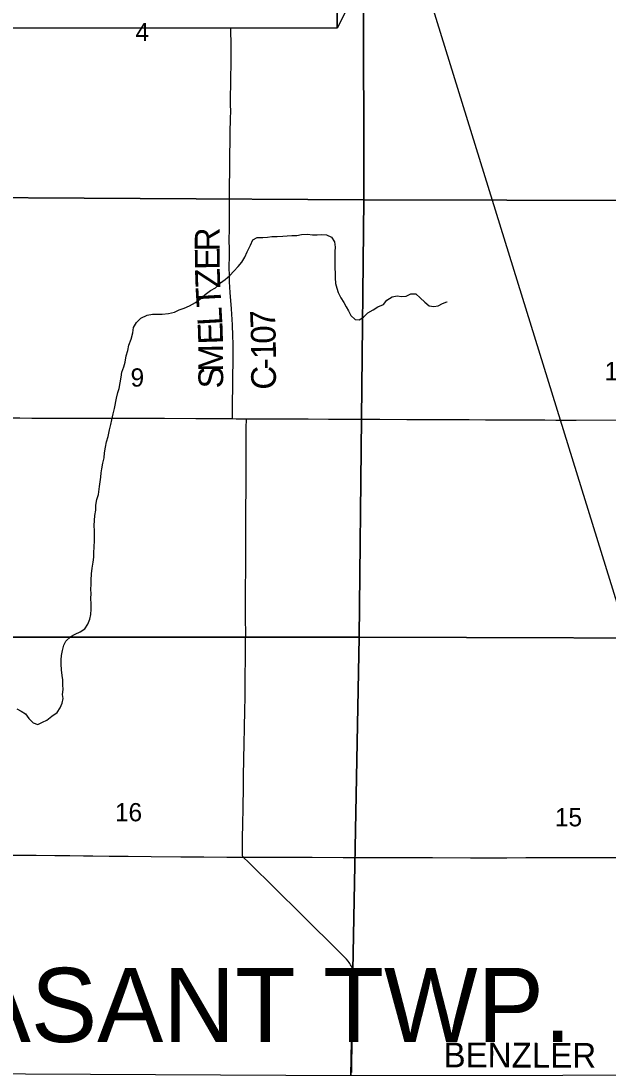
# Model space of a CAD drawing. Extents: x -97 to 34, y -21 to 22.
# Drawn here: x 4.799 to 6.147, y 14.464 to 16.869 of the extents above; entities that cross this region are included whole.
import ezdxf

# ---------------------------------------------------------------- set-up
doc = ezdxf.new("R2010")
doc.units = 0
for name, color, linetype in [('GM_X_County_Road', 7, 'Continuous'), ('GM_X_County_Road_Text', 7, 'Continuous'), ('GM_X_Minor_River', 7, 'Continuous'), ('GM_X_Rail_Line', 7, 'Continuous'), ('GM_X_Section', 7, 'Continuous'), ('GM_X_Section_Text', 7, 'Continuous'), ('GM_X_Township_Road_Text', 7, 'Continuous'), ('GM_X_Township_Text', 7, 'Continuous'), ('SH_Text', 7, 'Continuous')]:
    doc.layers.add(name, color=color, linetype=linetype)

msp = doc.modelspace()

# ---------------------------------------------------------------- linework, layer by layer
at = {"layer": 'GM_X_County_Road'}
for points in [[(5.285, 15.9558), (5.285, 15.9593), (5.2849, 15.9815), (5.2859, 16.0405), (5.2866, 16.0996), (5.2864, 16.1276), (5.286, 16.1462), (5.285, 16.1711), (5.2827, 16.2082), (5.28, 16.2455), (5.2784, 16.2703), (5.2778, 16.2858), (5.2776, 16.3013), (5.2778, 16.3324), (5.2778, 16.3446), (5.2777, 16.3664), (5.2779, 16.3913), (5.2779, 16.41), (5.278, 16.4255), (5.2783, 16.4659), (5.2785, 16.4846), (5.2784, 16.497), (5.2786, 16.5187), (5.2789, 16.5436), (5.279, 16.556), (5.2796, 16.5995), (5.28, 16.6119), (5.2808, 16.6461), (5.2809, 16.6616), (5.2808, 16.6772), (5.2807, 16.6896), (5.2808, 16.6989), (5.281, 16.7206), (5.2812, 16.7362), (5.2813, 16.7393), (5.2813, 16.7424), (5.2816, 16.7672), (5.2817, 16.7765), (5.2816, 16.7827), (5.2817, 16.7858), (5.2817, 16.7889), (5.2817, 16.792), (5.2819, 16.8106), (5.2812, 16.8527)], [(4.594, 15.9594), (4.6195, 15.9589), (4.6537, 15.9584), (4.6851, 15.958), (4.7283, 15.9579), (4.7625, 15.9577), (4.7967, 15.9573), (4.8246, 15.957), (4.8495, 15.9569), (4.8619, 15.9569), (4.9054, 15.9566), (4.9458, 15.9566), (4.9862, 15.9567), (5.0235, 15.9568), (5.0577, 15.9568), (5.0918, 15.9568), (5.1291, 15.9569), (5.2006, 15.9563), (5.2565, 15.9559), (5.285, 15.9558)], [(5.285, 15.9558), (5.2938, 15.9557), (5.3173, 15.9556)], [(5.3139, 15.3297), (5.3139, 15.3328), (5.3141, 15.3639), (5.3146, 15.4043), (5.3151, 15.4478), (5.3153, 15.4634), (5.315, 15.4945), (5.3149, 15.5287), (5.3152, 15.5691), (5.3155, 15.6064), (5.3154, 15.6189), (5.3154, 15.6344), (5.3154, 15.6624), (5.3158, 15.7059), (5.3159, 15.7339), (5.316, 15.7557), (5.3161, 15.7865), (5.3162, 15.8024), (5.3164, 15.8241), (5.3165, 15.8677), (5.3164, 15.8956), (5.3164, 15.9174), (5.3165, 15.9268), (5.3167, 15.9359), (5.3172, 15.9529), (5.3173, 15.9556)], [(5.3173, 15.9556), (5.328, 15.9555), (5.4181, 15.9551), (5.4585, 15.9551), (5.5051, 15.9549), (5.6232, 15.9543), (5.6854, 15.9539), (5.7476, 15.954), (5.7817, 15.9537), (5.8284, 15.9536), (5.8656, 15.9532), (5.8998, 15.9533), (5.9713, 15.9531), (6.0024, 15.9528), (6.0272, 15.9524), (6.0397, 15.9524), (6.0738, 15.9525), (6.1795, 15.9528)], [(5.31, 14.948), (5.3095, 14.9486), (5.3088, 14.9498), (5.3082, 14.9512), (5.3078, 14.9525), (5.3076, 14.954), (5.3076, 14.9554), (5.3079, 14.9833), (5.309, 15.033), (5.3094, 15.0516), (5.3094, 15.0703), (5.3099, 15.1013), (5.3105, 15.1355), (5.312, 15.21), (5.3124, 15.2442), (5.3133, 15.2876), (5.3138, 15.3138), (5.3139, 15.3297)], [(4.5259, 14.9544), (4.5326, 14.9543), (4.5823, 14.9538), (4.6444, 14.9529), (4.7034, 14.9529), (4.7314, 14.9528), (4.7749, 14.9529), (4.8339, 14.9526), (4.8773, 14.952), (4.9115, 14.9519), (4.9426, 14.9516), (4.9643, 14.9513), (5.0016, 14.9509), (5.0451, 14.9504), (5.0979, 14.9499), (5.1663, 14.9494), (5.2191, 14.949), (5.2719, 14.9485), (5.31, 14.948)], [(5.31, 14.948), (5.3154, 14.948), (5.3558, 14.9483), (5.4677, 14.9483), (5.5392, 14.9479), (5.6168, 14.9479), (5.6665, 14.9473), (5.6883, 14.9473), (5.7442, 14.9474), (5.8313, 14.9469), (5.8748, 14.9466), (5.8965, 14.9467), (5.9152, 14.9468), (5.9587, 14.9473), (5.9866, 14.9473), (6.0612, 14.9474), (6.1762, 14.9477), (6.2166, 14.9476), (6.2694, 14.9473), (6.2946, 14.9471)], [(5.5587, 14.4535), (5.5592, 14.4815), (5.5598, 14.5094), (5.5605, 14.5467), (5.5622, 14.6274), (5.5628, 14.6585), (5.563, 14.674), (5.5627, 14.6803), (5.5624, 14.6835), (5.5618, 14.6866), (5.5611, 14.6896), (5.5602, 14.6927), (5.559, 14.6956), (5.5577, 14.6985), (5.5562, 14.7013), (5.5545, 14.704), (5.5527, 14.7065), (5.5507, 14.709), (5.5466, 14.7138), (5.5423, 14.7183), (5.527, 14.7337), (5.5006, 14.76), (5.4762, 14.7839), (5.4321, 14.8277), (5.3945, 14.8648), (5.3747, 14.8845), (5.3613, 14.8975), (5.3458, 14.9127), (5.3193, 14.9389), (5.3124, 14.9452), (5.3104, 14.9474), (5.31, 14.948)]]:
    msp.add_lwpolyline(points, dxfattribs=at)
at = {"layer": 'GM_X_Minor_River'}
for points in [[(5.0313, 16.0624), (5.0357, 16.0748), (5.0385, 16.0858), (5.041, 16.0998), (5.0446, 16.1126), (5.0467, 16.1247), (5.0526, 16.1386), (5.0559, 16.153), (5.0576, 16.1654), (5.0649, 16.1763), (5.0746, 16.1868), (5.089, 16.1937), (5.1012, 16.1958), (5.1125, 16.1959), (5.1239, 16.1958), (5.1379, 16.1974), (5.1519, 16.2006), (5.1626, 16.2057), (5.1744, 16.2093), (5.1865, 16.2148), (5.1999, 16.2229), (5.2125, 16.2317), (5.2221, 16.2407), (5.2348, 16.2499), (5.2458, 16.2562), (5.2577, 16.2674), (5.2681, 16.2755), (5.2788, 16.2844), (5.2884, 16.2949), (5.2977, 16.3053), (5.3065, 16.315), (5.3132, 16.3271), (5.3187, 16.3391), (5.3265, 16.3541), (5.332, 16.3669), (5.3419, 16.372), (5.3544, 16.3718), (5.3653, 16.3728), (5.3756, 16.3741), (5.3877, 16.3739), (5.4005, 16.3748), (5.4108, 16.3758), (5.4214, 16.3767), (5.4327, 16.3769), (5.4433, 16.3786), (5.457, 16.3799), (5.4686, 16.3778), (5.4792, 16.3784), (5.4894, 16.3786), (5.5008, 16.3784), (5.512, 16.3725), (5.5194, 16.3622), (5.5207, 16.3496), (5.5202, 16.3394), (5.52, 16.3261), (5.5201, 16.3151), (5.5203, 16.3015), (5.5205, 16.2897), (5.5207, 16.2791), (5.5212, 16.2666), (5.5245, 16.2555), (5.5273, 16.2453), (5.5339, 16.2334), (5.5405, 16.2227), (5.546, 16.2127), (5.5512, 16.2031), (5.5567, 16.1924), (5.5663, 16.1832), (5.5762, 16.183), (5.5861, 16.1889), (5.5961, 16.199), (5.6076, 16.2056), (5.6186, 16.2126), (5.6319, 16.2177), (5.6397, 16.2282), (5.6515, 16.2359), (5.6633, 16.238), (5.6731, 16.2367), (5.6837, 16.2369), (5.6944, 16.2427), (5.7061, 16.2425), (5.7161, 16.2337), (5.7266, 16.2236), (5.7362, 16.2151), (5.7476, 16.2134), (5.7574, 16.2151), (5.7673, 16.2203), (5.7769, 16.2243), (5.7772, 16.2235)], [(4.7901, 15.2891), (4.7999, 15.284), (4.8096, 15.2778), (4.8173, 15.2666), (4.8277, 15.2566), (4.8379, 15.253), (4.849, 15.2585), (4.8585, 15.2629), (4.87, 15.2722), (4.8822, 15.2807), (4.8892, 15.2916), (4.8939, 15.3021), (4.896, 15.3127), (4.895, 15.3222), (4.8959, 15.3335), (4.8954, 15.3445), (4.8955, 15.3555), (4.8942, 15.3658), (4.8925, 15.3787), (4.892, 15.3916), (4.8914, 15.4015), (4.8927, 15.4113), (4.8944, 15.4234), (4.8976, 15.4351), (4.9023, 15.4449), (4.9135, 15.4549), (4.9241, 15.4604), (4.9352, 15.4663), (4.9463, 15.4729), (4.9532, 15.4834), (4.9572, 15.4951), (4.96, 15.5056), (4.9603, 15.5182), (4.9608, 15.5299), (4.9599, 15.5432), (4.9605, 15.5534), (4.9599, 15.564), (4.9608, 15.575), (4.9606, 15.5849), (4.9616, 15.5989), (4.9629, 15.6121), (4.9651, 15.6261), (4.9664, 15.6378), (4.9669, 15.6477), (4.9675, 15.6613), (4.9682, 15.6753), (4.9684, 15.6882), (4.9682, 15.6984), (4.9676, 15.7106), (4.9682, 15.722), (4.9687, 15.7329), (4.9712, 15.7458), (4.9714, 15.7572), (4.9739, 15.77), (4.9775, 15.7817), (4.9793, 15.7995), (4.9814, 15.8104), (4.9827, 15.821), (4.9836, 15.8309), (4.9853, 15.8407), (4.9874, 15.8535), (4.9902, 15.866), (4.9912, 15.8774), (4.9937, 15.8906), (4.9957, 15.9027), (4.9994, 15.9147), (5.003, 15.9302), (5.0055, 15.9423), (5.0083, 15.9532), (5.0112, 15.9665), (5.014, 15.9793), (5.019, 16.0027), (5.0218, 16.0156), (5.0246, 16.0254), (5.0271, 16.0378), (5.0292, 16.0511), (5.0313, 16.0624)]]:
    msp.add_lwpolyline(points, dxfattribs=at)
at = {"layer": 'GM_X_Rail_Line'}
msp.add_lwpolyline([(6.6358, 14.0177), (6.5035, 14.4453), (6.467, 14.5631), (6.2643, 15.2201), (6.0384, 15.9521), (5.7262, 16.962), (5.6052, 17.3534)], dxfattribs=at)
at = {"layer": 'GM_X_Section'}
for points in [[(4.5827, 17.473), (5.5851, 17.4654), (5.5865, 16.4584), (4.5591, 16.4647)], [(5.5851, 17.4654), (6.5942, 17.463), (6.5713, 16.4562), (5.5865, 16.4584)], [(4.5591, 16.4647), (5.5865, 16.4584), (5.5758, 15.4541), (4.5367, 15.4537)], [(5.5865, 16.4584), (6.5713, 16.4562), (6.5605, 15.4504), (5.5758, 15.4541)], [(4.5367, 15.4537), (5.5758, 15.4541), (5.5564, 14.4458), (4.5101, 14.4515)], [(5.5758, 15.4541), (6.5605, 15.4504), (6.5304, 14.4478), (5.5564, 14.4458)]]:
    msp.add_lwpolyline(points, close=True, dxfattribs=at)
at = {"layer": 'SH_Text'}
for points in [[(5.5255, 17.3534), (6.1456, 18.0821), (5.5255, 16.8527)], [(3.6076, 17.3534), (5.5255, 17.3534), (5.5255, 16.8527), (3.6076, 16.8527)]]:
    msp.add_lwpolyline(points, close=True, dxfattribs=at)

# ---------------------------------------------------------------- texts
at = {"layer": 'GM_X_County_Road_Text'}
for s, rotation, p in [('R', 90.0039, (5.2553, 16.3402)), ('E', 90.4843, (5.2557, 16.2978)), ('Z', 92.0147, (5.2572, 16.2558)), ('T', 93.2892, (5.2596, 16.2137)), ('L', 93.2343, (5.262, 16.1712)), ('7', 92.3639, (5.3837, 16.1648)), ('E', 91.8181, (5.2634, 16.1272)), ('0', 91.0325, (5.3844, 16.1284)), ('M', 90.2027, (5.2636, 16.0638)), ('1', 90.4074, (5.3847, 16.0927)), ('S', 89.9905, (5.2636, 16.0252)), ('C', 90.0117, (5.3847, 16.0223)), ('-', 90.1079, (5.3847, 16.0691))]:
    msp.add_text(s, height=0.0568, rotation=rotation, dxfattribs=at).set_placement(p)
at = {"layer": 'GM_X_Section_Text'}
for s, height, p in [('4', 0.0419, (5.0622, 16.8231)), ('9', 0.0419, (5.051, 16.0294)), ('10', 0.04186, (6.1393, 16.044)), ('16', 0.04186, (5.0152, 15.0307)), ('15', 0.04186, (6.0252, 15.0191))]:
    msp.add_text(s, height=height, rotation=0, dxfattribs=at).set_placement(p)
at = {"layer": 'GM_X_Township_Road_Text'}
msp.add_text('BENZLER', height=0.05682, rotation=359.848, dxfattribs=at).set_placement((5.7695, 14.4655))
at = {"layer": 'GM_X_Township_Text'}
msp.add_text('PLEASANT TWP.', height=0.170455, rotation=0, dxfattribs=at).set_placement((4.2393, 14.5235))

doc.saveas('drawing.dxf')
